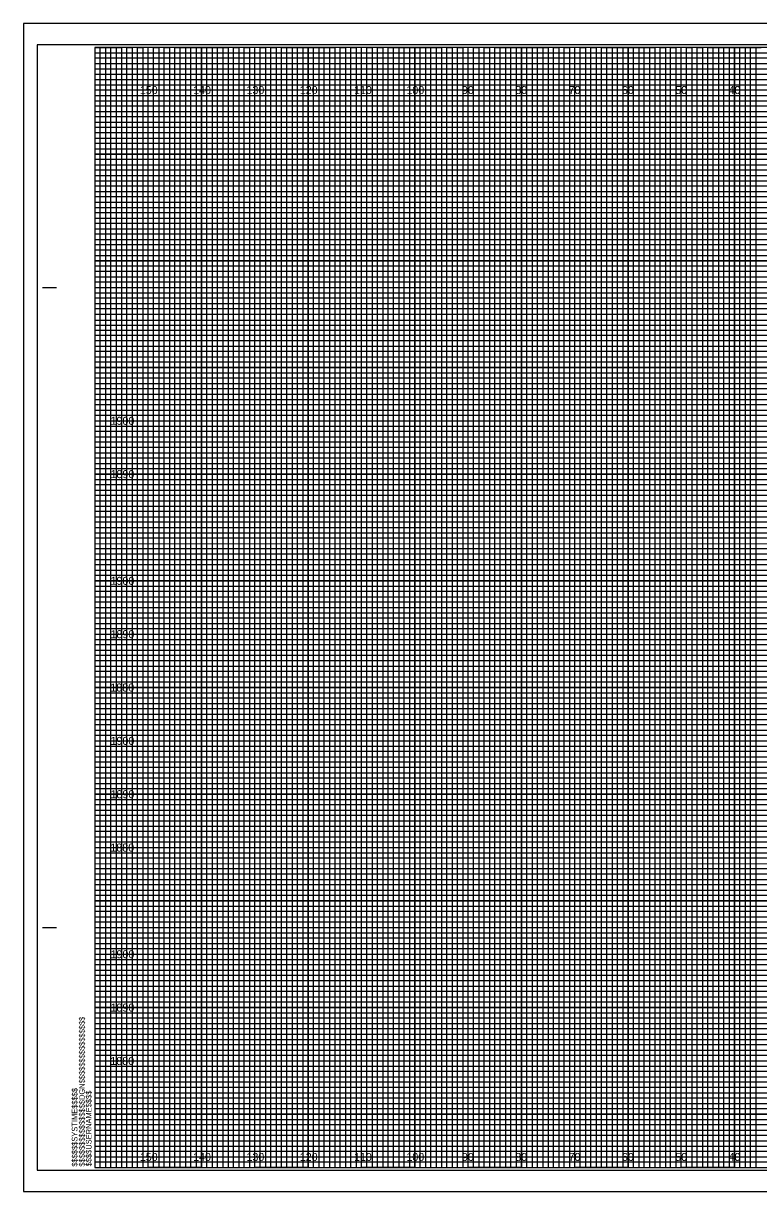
# Model space of a CAD drawing. Extents: x -13 to 323, y -4 to 214.
# Drawn here: x -13.4 to 124.5, y -4.5 to 214.5 of the extents above; entities that cross this region are included whole.
import ezdxf

# ---------------------------------------------------------------- set-up
doc = ezdxf.new("R2010")
doc.units = 0
for name, color, linetype in [('Prop XS Elevation Labels', 7, 'Continuous'), ('Prop XS Offset Labels', 7, 'Continuous'), ('Sheet Cross Section CELL', 7, 'Continuous'), ('Sheet Cross Section Grid Major CELL', 7, 'Continuous'), ('Sheet Cross Section Grid Middle CELL', 7, 'Continuous'), ('Sheet Cross Section Grid Minor 1 CELL', 7, 'Continuous'), ('Sheet Cross Section Grid Minor 2 CELL', 7, 'Continuous'), ('Sheet Cutting Line CELL', 7, 'Continuous'), ('Sheet DOT Grid CELL', 7, 'Continuous'), ('Sheet Plot Border Inside CELL', 7, 'Continuous'), ('Sheet Plot Border Outside CELL', 7, 'Continuous')]:
    doc.layers.add(name, color=color, linetype=linetype)

msp = doc.modelspace()

# ---------------------------------------------------------------- linework, layer by layer
at = {"layer": 'Sheet Cross Section CELL'}
for p, q in [((-9.8, 165), (-7.3, 165)), ((-9.7, 165), (-7.2, 165)), ((-9.8, 45), (-7.3, 45)), ((-9.7, 45), (-7.2, 45))]:
    msp.add_line(p, q, dxfattribs=at)
msp.add_lwpolyline([(320, 210), (0, 210), (0, 0), (320, 0)], close=True, dxfattribs=at)
at = {"layer": 'Sheet Cross Section Grid Major CELL'}
for p, q in [((10, 210), (0, 210)), ((10, 0), (10, 210)), ((30, 210), (20, 210)), ((20, 210), (20, 0)), ((30, 0), (30, 210)), ((50, 210), (40, 210)), ((40, 210), (40, 0)), ((50, 0), (50, 210)), ((70, 210), (60, 210)), ((60, 210), (60, 0)), ((70, 0), (70, 210)), ((90, 210), (80, 210)), ((80, 210), (80, 0)), ((90, 0), (90, 210)), ((110, 210), (100, 210)), ((100, 210), (100, 0)), ((110, 0), (110, 210)), ((130, 210), (120, 210)), ((120, 210), (120, 0)), ((20, 0), (10, 0)), ((40, 0), (30, 0)), ((60, 0), (50, 0)), ((80, 0), (70, 0)), ((100, 0), (90, 0)), ((120, 0), (110, 0))]:
    msp.add_line(p, q, dxfattribs=at)
for points in [[(0, 200), (320, 200), (320, 190), (0, 190)], [(0, 180), (320, 180), (320, 170), (0, 170)], [(0, 160), (320, 160), (320, 150), (0, 150)], [(0, 140), (320, 140), (320, 130), (0, 130)], [(0, 120), (320, 120), (320, 110), (0, 110)], [(0, 100), (320, 100), (320, 90), (0, 90)], [(0, 80), (320, 80), (320, 70), (0, 70)], [(0, 60), (320, 60), (320, 50), (0, 50)], [(0, 40), (320, 40), (320, 30), (0, 30)], [(0, 20), (320, 20), (320, 10), (0, 10)]]:
    msp.add_lwpolyline(points, dxfattribs=at)
at = {"layer": 'Sheet Cross Section Grid Middle CELL'}
for points in [[(0, 210), (5, 210), (5, 0), (15, 0), (15, 210), (25, 210), (25, 0), (35, 0), (35, 210), (45, 210), (45, 0), (55, 0), (55, 210), (65, 210), (65, 0), (75, 0), (75, 210), (85, 210), (85, 0), (95, 0), (95, 210), (105, 210), (105, 0), (115, 0), (115, 210), (125, 210)], [(0, 205), (275, 205)], [(0, 185), (320, 185), (320, 195), (0, 195)], [(0, 165), (320, 165), (320, 175), (0, 175)], [(0, 145), (320, 145), (320, 155), (0, 155)], [(0, 125), (320, 125), (320, 135), (0, 135)], [(0, 105), (320, 105), (320, 115), (0, 115)], [(0, 85), (320, 85), (320, 95), (0, 95)], [(0, 65), (320, 65), (320, 75), (0, 75)], [(0, 45), (320, 45), (320, 55), (0, 55)], [(0, 25), (320, 25), (320, 35), (0, 35)], [(0, 5), (320, 5), (320, 15), (0, 15)]]:
    msp.add_lwpolyline(points, dxfattribs=at)
at = {"layer": 'Sheet Cross Section Grid Minor 1 CELL'}
for p, q in [((0, 209), (260, 209)), ((260, 207.98), (0, 207.98)), ((0, 207.98), (0, 207)), ((0, 207), (260, 207)), ((260, 205.89), (0, 205.89)), ((0, 205.89), (0, 204)), ((0, 204), (320, 204))]:
    msp.add_line(p, q, dxfattribs=at)
for points in [[(0, 203), (270, 203), (320, 203), (320, 202), (0, 202)], [(0, 201), (320, 201), (320, 199), (0, 199)], [(0, 198), (320, 198), (320, 197), (0, 196.98)], [(0, 196), (320, 196), (320, 194), (0, 194)], [(0, 193), (320, 193), (320, 192), (0, 192)], [(0, 191), (320, 191), (320, 189), (0, 189)], [(0, 188), (320, 188), (320, 187), (0, 187)], [(0, 186), (320, 186), (320, 184), (0, 184)], [(0, 183), (320, 183), (320, 182), (0, 182)], [(0, 181), (320, 181), (320, 179), (0, 179)], [(0, 178), (320, 178), (320, 177), (0, 177)], [(0, 176), (320, 176), (320, 173.95), (320, 173), (320, 172), (0, 172)], [(0, 174), (320, 174), (320, 173), (0, 173)], [(0, 171), (320, 171), (320, 169), (0, 169.03)], [(0, 169.03), (320, 169), (320, 168), (0, 168)], [(0, 167), (320, 167), (320, 166), (0, 166)], [(0, 164), (320, 164), (320, 163), (0, 163)], [(0, 162), (320, 162), (320, 161), (0, 161)], [(-0.07, 158.89), (320, 158.89), (320, 157.88), (-0.07, 157.88)], [(0, 157), (320, 157), (320, 156), (0, 156)], [(0, 154), (320, 154), (320, 153), (0, 153)], [(0, 152), (320, 152), (320, 151), (0, 151)], [(0, 149), (320, 149), (320, 148), (0, 148)], [(0, 147), (320, 147), (320, 146), (0, 146)], [(0, 144), (320, 144), (320, 143), (0, 143)], [(0, 142), (320, 142), (320, 141), (0, 141)], [(0, 139), (320, 139), (319.99, 137.98), (0, 138)], [(0, 137), (320, 137), (320, 136), (0, 136)], [(0, 134), (320, 134), (320, 133), (0, 133)], [(0, 132), (320, 132), (320, 131), (0, 131)], [(0, 129), (320, 129), (320, 128), (0, 128)], [(0, 127), (320, 127), (320, 126), (0, 126)], [(0, 124), (320, 124), (320, 123), (0, 123)], [(0, 122), (320, 122), (320, 121), (0, 121)], [(0, 119), (320, 119), (320, 118), (0, 118)], [(0, 116.99), (320.07, 116.91), (320, 116), (0, 116)], [(0, 114), (320, 114), (320, 113), (0, 113)], [(0, 112), (320, 112), (320, 111), (0, 111)], [(0, 109), (320, 109), (320, 108), (0, 108)], [(0, 107), (320, 107), (320, 106), (0, 106)], [(0, 104), (320, 104), (320, 103), (0, 103)], [(0, 102), (320, 102), (320, 101), (0, 101)], [(0, 99), (320, 99), (320, 98), (0, 98)], [(0, 97), (320, 97), (320, 96), (0, 96)], [(0, 94), (320, 94), (320, 93), (0, 93)], [(0, 92), (320, 92), (320, 91), (0, 91)], [(0, 89), (320, 89), (320, 88), (0, 88)], [(0, 87), (320, 87), (320, 86), (0, 86)], [(0, 84), (320, 84), (320, 83), (0, 83)], [(0, 82), (320, 82), (320, 81), (0, 81)], [(0, 79), (320, 79), (319.99, 77.98), (0, 78)], [(0, 77), (320, 77), (320, 76), (0, 76)], [(0, 74), (320, 74), (320, 73), (0, 73)], [(0, 72), (320, 72), (320, 71), (0, 71)], [(0, 69), (320, 69), (320, 68), (0, 68)], [(0, 67), (320, 67), (320, 66), (0, 66)], [(0, 64), (320, 64), (320, 63), (0, 63)], [(0, 62), (320, 62), (320, 61), (0, 61)], [(0, 59), (320, 59), (320, 58), (0, 58)], [(0, 56.99), (320.07, 56.91), (320, 56), (0, 56)], [(0, 54), (320, 54), (320, 53), (0, 53)], [(0, 52), (320, 52), (320, 51), (0, 51)], [(0, 49), (320, 49), (320, 48), (0, 48)], [(0, 47), (320, 47), (320, 46), (0, 46)], [(0, 44), (320, 44), (320, 43), (0, 43)], [(0, 42), (320, 42), (320, 41), (0, 41)], [(0, 39), (320, 39), (320, 38), (0, 38)], [(0, 37), (320, 37), (320, 36), (0, 36)], [(0, 34), (320, 34), (320, 33), (0, 33)], [(0, 32), (320, 32), (320, 31), (0, 31)], [(0, 29), (320, 29), (320, 28), (0, 28)], [(0, 27), (320, 27), (320, 26), (0, 26)], [(0, 24), (320, 24), (320, 23), (0, 23)], [(0, 22), (320, 22), (320, 21), (0, 21)], [(0, 19), (320, 19), (320, 18), (0, 18)], [(0, 17), (320, 17), (320, 16), (0, 16)], [(0, 14), (320, 14), (320, 13), (0, 13)], [(0, 12), (320, 12), (320, 11), (0, 11)], [(0, 9), (320, 9), (320, 8), (0, 8)], [(0, 7), (320, 7), (320, 6), (0, 6)], [(0, 4), (320, 4), (320, 3), (0, 3)], [(0, 2), (320, 2), (320, 1), (0, 1)]]:
    msp.add_lwpolyline(points, dxfattribs=at)
at = {"layer": 'Sheet Cross Section Grid Minor 2 CELL'}
for points in [[(0, 0), (1, 0), (1, 210), (2, 210), (2, 0)], [(2, 0), (3, 0), (3, 210), (4, 210), (4, 0)], [(5, 0), (6, 0), (6, 210), (7, 210), (7, 0)], [(7, 0), (8, 0), (8, 210), (9, 210), (9, 0)], [(10, 0), (11, 0), (11, 210), (12, 210), (12, 0)], [(12, 0), (13, 0), (13, 210), (14, 210), (14, 0)], [(15, 0), (16, 0), (16, 210), (17, 210), (17, 0)], [(17, 0), (18, 0), (18, 210), (19, 210), (19, 0)], [(20, 0), (21, 0), (21, 210), (22, 210), (22, 0)], [(22, 0), (23, 0), (23, 210), (24, 210), (24, 0)], [(25, 0), (26, 0), (26, 210), (27, 210), (27, 0)], [(27, 0), (28, 0), (28, 210), (29, 210), (29, 0)], [(30, 0), (31, 0), (31, 210), (32, 210), (32, 0)], [(32, 0), (33, 0), (33, 210), (34, 210), (34, 0)], [(35, 0), (36, 0), (36, 210), (37, 210), (37, 0)], [(37, 0), (38, 0), (38, 210), (39, 210), (39, 0)], [(40, 0), (41, 0), (41, 210), (42, 210), (42, 0)], [(42, 0), (43, 0), (43, 210), (44, 210), (44, 0)], [(45, 0), (46, 0), (46, 210), (47, 210), (47, 0)], [(47, 0), (48, 0), (48, 210), (49, 210), (49, 0)], [(50, 0), (51, 0), (51, 210), (52, 210), (52, 0)], [(52, 0), (53, 0), (53, 210), (54, 210), (54, 0)], [(55, 0), (56, 0), (56, 210), (57, 210), (57, 0)], [(57, 0), (58, 0), (58, 210), (59, 210), (59, 0)], [(60, 0), (61, 0), (61, 210), (62, 210), (62, 0)], [(62, 0), (63, 0), (63, 210), (64, 210), (64, 0)], [(65, 0), (66, 0), (66, 210), (67, 210), (67, 0)], [(67, 0), (68, 0), (68, 210), (69, 210), (69, 0)], [(70, 0), (71, 0), (71, 210), (72, 210), (72, 0)], [(72, 0), (73, 0), (73, 210), (74, 210), (74, 0)], [(75, 0), (76, 0), (76, 210), (77, 210), (77, 0)], [(77, 0), (78, 0), (78, 210), (79, 210), (79, 0)], [(80, 0), (81, 0), (81, 210), (82, 210), (82, 0)], [(82, 0), (83, 0), (83, 210), (84, 210), (84, 0)], [(85, 0), (86, 0), (86, 210), (87, 210), (87, 0)], [(87, 0), (88, 0), (88, 210), (89, 210), (89, 0)], [(90, 0), (91, 0), (91, 210), (92, 210), (92, 0)], [(92, 0), (93, 0), (93, 210), (94, 210), (94, 0)], [(95, 0), (96, 0), (96, 210), (97, 210), (97, 0)], [(97, 0), (98, 0), (98, 210), (99, 210), (99, 0)], [(100, 0), (101, 0), (101, 210), (102, 210), (102, 0)], [(102, 0), (103, 0), (103, 210), (104, 210), (104, 0)], [(105, 0), (106, 0), (106, 210), (107, 210), (107, 0)], [(107, 0), (108, 0), (108, 210), (109, 210), (109, 0)], [(110, 0), (111, 0), (111, 210), (112, 210), (112, 0)], [(112, 0), (113, 0), (113, 210), (114, 210), (114, 0)], [(115, 0), (116, 0), (116, 210), (117, 210), (117, 0)], [(117, 0), (118, 0), (118, 210), (119, 210), (119, 0)], [(120, 0), (121, 0), (121, 210), (122, 210), (122, 0)], [(122, 0), (123, 0), (123, 210), (124, 210), (124, 0)]]:
    msp.add_lwpolyline(points, dxfattribs=at)
at = {"layer": 'Sheet Cutting Line CELL'}
for p, q in [((323.3, 214.5), (-13.4, 214.5)), ((-13.4, 214.5), (-13.4, -4.5)), ((-13.4, -4.5), (323.3, -4.5))]:
    msp.add_line(p, q, dxfattribs=at)
at = {"layer": 'Sheet DOT Grid CELL'}
for p, q in [((10, 0), (10, 210)), ((20, 0), (20, 210)), ((30, 0), (30, 210)), ((40, 0), (40, 210)), ((50, 0), (50, 210)), ((60, 0), (60, 210)), ((70, 0), (70, 210)), ((80, 0), (80, 210)), ((90, 0), (90, 210)), ((100, 0), (100, 210)), ((110, 0), (110, 210)), ((120, 0), (120, 210)), ((0, 200), (320, 200)), ((0, 190), (320, 190)), ((0, 180), (320, 180)), ((0, 170), (320, 170)), ((0, 160), (320, 160)), ((0, 150), (320, 150)), ((0, 140), (320, 140)), ((0, 130), (320, 130)), ((0, 120), (320, 120)), ((0, 110), (320, 110)), ((0, 100), (320, 100)), ((0, 90), (320, 90)), ((0, 80), (320, 80)), ((0, 70), (320, 70)), ((0, 60), (320, 60)), ((0, 50), (320, 50)), ((0, 40), (320, 40)), ((0, 30), (320, 30)), ((0, 20), (320, 20)), ((0, 10), (320, 10))]:
    msp.add_line(p, q, dxfattribs=at)
at = {"layer": 'Sheet Plot Border Inside CELL'}
msp.add_lwpolyline([(-10.8, -0.5), (322.4, -0.5), (322.4, 210.5), (-10.8, 210.5)], close=True, dxfattribs=at)
at = {"layer": 'Sheet Plot Border Outside CELL'}
msp.add_lwpolyline([(-13.4, -4.5), (323.3, -4.5), (323.3, 214.5), (-13.4, 214.5)], close=True, dxfattribs=at)

# ---------------------------------------------------------------- texts
at = {"layer": 'Prop XS Elevation Labels'}
for s, p in [('1900', (2.95, 139.25)), ('1890', (2.95, 129.25)), ('1900', (2.95, 109.25)), ('1890', (2.95, 99.25)), ('1880', (2.92, 89.25)), ('1900', (2.95, 79.25)), ('1890', (2.95, 69.25)), ('1880', (2.92, 59.25)), ('1900', (2.95, 39.25)), ('1890', (2.95, 29.25)), ('1880', (2.92, 19.25))]:
    msp.add_text(s, height=1.5, dxfattribs=at).set_placement(p)
at = {"layer": 'Prop XS Offset Labels'}
for s, p in [('150', (8.44, 201.25)), ('140', (18.44, 201.25)), ('130', (28.44, 201.25)), ('120', (38.44, 201.25)), ('110', (48.62, 201.25)), ('100', (58.44, 201.25)), ('90', (68.86, 201.25)), ('80', (78.86, 201.25)), ('70', (88.86, 201.25)), ('60', (98.86, 201.25)), ('50', (108.86, 201.25)), ('40', (118.86, 201.25)), ('150', (8.44, 1.25)), ('140', (18.44, 1.25)), ('130', (28.44, 1.25)), ('120', (38.44, 1.25)), ('110', (48.62, 1.25)), ('100', (58.44, 1.25)), ('90', (68.86, 1.25)), ('80', (78.86, 1.25)), ('70', (88.86, 1.25)), ('60', (98.86, 1.25)), ('50', (108.86, 1.25)), ('40', (118.86, 1.25))]:
    msp.add_text(s, height=1.5, dxfattribs=at).set_placement(p)
at = {"layer": 'Sheet Cross Section CELL'}
for s, p in [('$$$$$$$$$$$$$$$$DGN$$$$$$$$$$$$$$$$', (-1.88, 0.18)), ('$$$$$$SYSTIME$$$$$', (-3.26, 0.18)), ('$$$$USERNAME$$$$', (-0.62, 0.23))]:
    msp.add_text(s, height=1.05, rotation=90, dxfattribs=at).set_placement(p)

doc.saveas('drawing.dxf')
